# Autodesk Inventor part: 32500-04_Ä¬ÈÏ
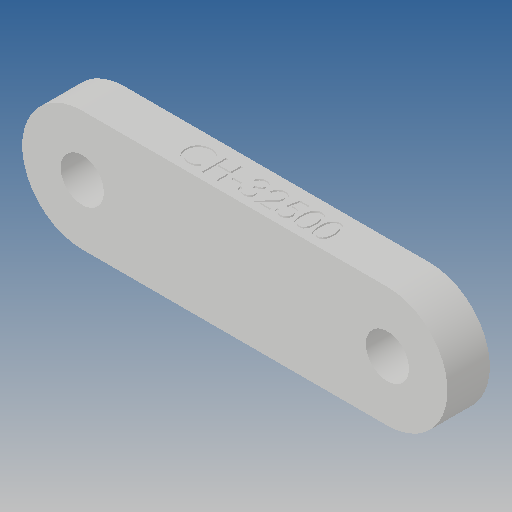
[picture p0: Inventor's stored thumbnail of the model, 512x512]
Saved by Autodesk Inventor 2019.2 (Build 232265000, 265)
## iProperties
Created: 2010-06
Part Number: 32500-04_Ä¬ÈÏ
Material: Ogólny
Document SubType Name: Modeling
Designer: CADENGINEERING4
Density: 1 g/cm^3
Appearance: Domyślna
Author: CADENGINEERING4
Revision Number: ÈÎºÎ
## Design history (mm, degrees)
feature "NONE"
node "Bryła1"
